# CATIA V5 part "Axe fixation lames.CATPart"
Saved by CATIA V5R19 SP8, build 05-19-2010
Part number: Axe fixation lames
Bounding box of the stored display mesh (mm): x 0 to 24, y -6 to 6, z -5.85 to 5.85
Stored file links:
  G:\EU_thinkMotion\CFAO_2010\MMS_groupe2\MMS_groupe2\A reprendre\rbouchet\rbouchet_Catia\Axe fixation lames.CATPart
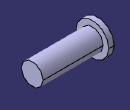
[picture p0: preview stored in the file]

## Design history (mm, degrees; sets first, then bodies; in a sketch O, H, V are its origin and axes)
Body1 (main body)
  Sketch1 on yz-plane, origin (0, 0, 0), H (0, 1, 0), V (0, 0, 1)
    circle A1 centre (0, 0) radius 6
    radius A1 = 6
  Pad1: profile Sketch1, direction (1, 0, 0), length 2
  Sketch2 on end face of Pad1, origin (2, 0, 0), H (0, 1, 0), V (0, 0, 1)
    circle A1 centre (0, 0) radius 4
    radius A1 = 4
  Pad2: profile Sketch2, direction (1, 0, 0), length 22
